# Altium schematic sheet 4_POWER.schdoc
size 749 x 139 mm
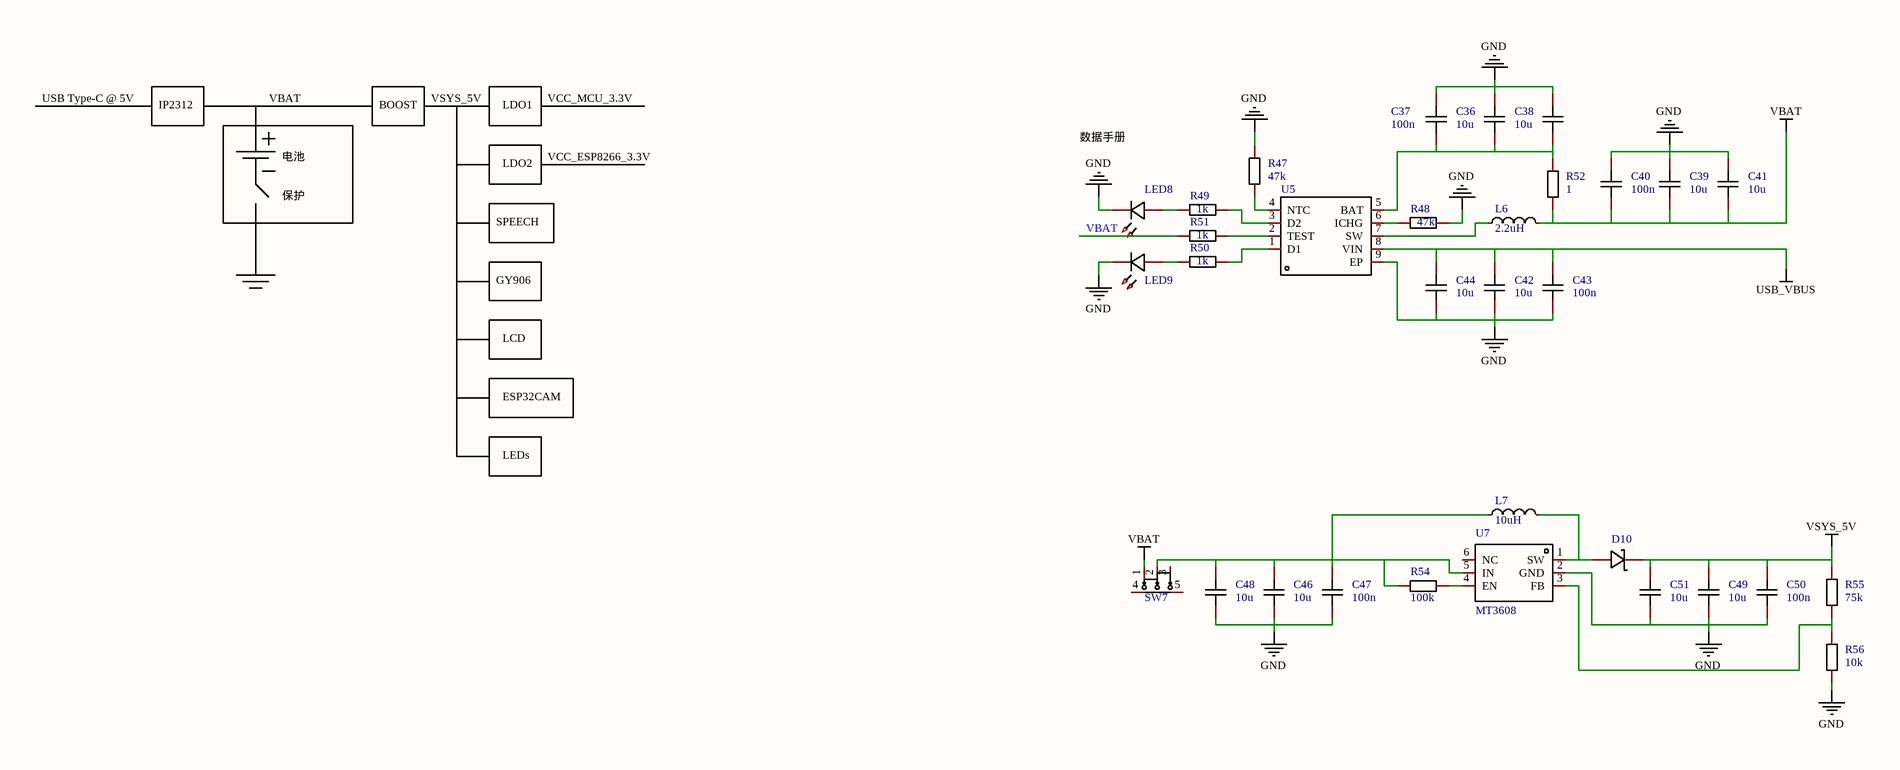
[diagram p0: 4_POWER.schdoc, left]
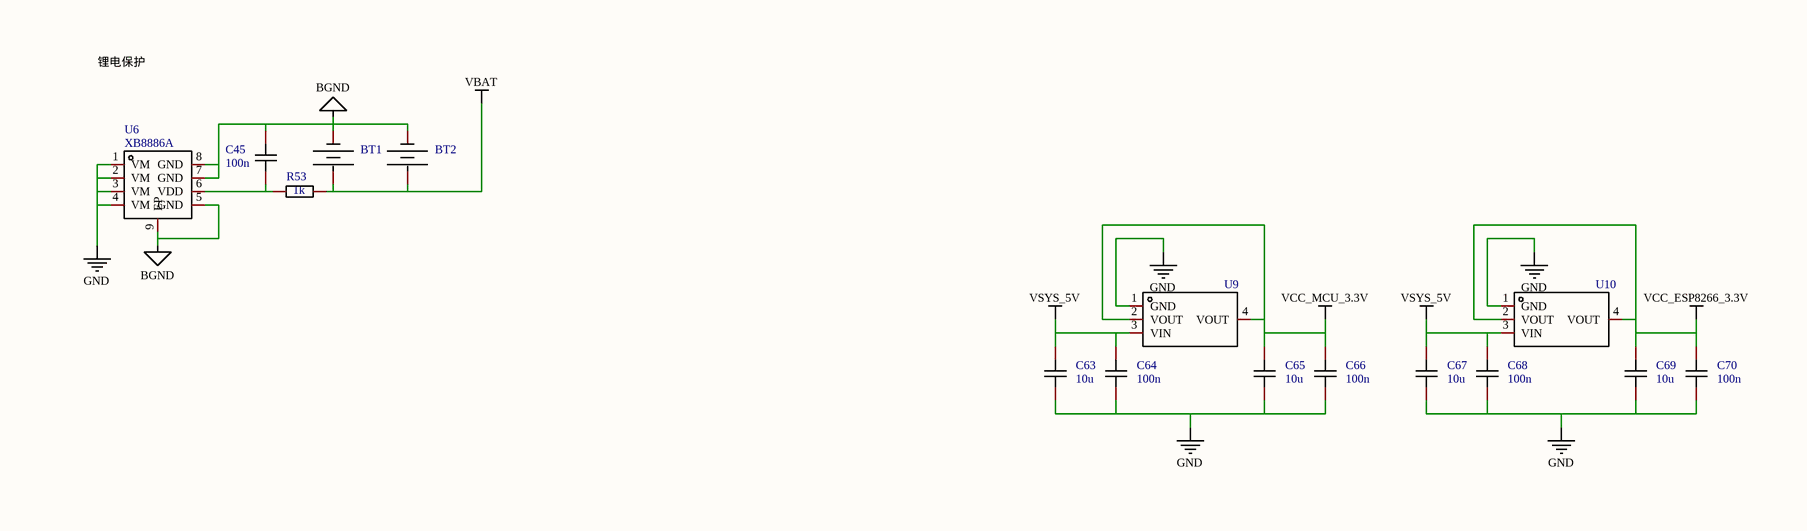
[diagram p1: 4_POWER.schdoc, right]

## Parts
BT1  1028  [BAT-TH_KEYSTONE-1028]  (value not drawn)
BT2  1028  [BAT-TH_KEYSTONE-1028]  (value not drawn)
C36  10u  [C0603]
C37  100n  [C0603]
C38  10u  [C0603]
C39  10u  [C0603]
C40  100n  [C0603]
C41  10u  [C0603]
C42  10u  [C0603]
C43  100n  [C0603]
C44  10u  [C0603]
C45  100n  [C0603]
C46  10u  [C0603]
C47  100n  [C0603]
C48  10u  [C0603]
C49  10u  [C0603]
C50  100n  [C0603]
C51  10u  [C0603]
C63  10u  [C0603]
C64  100n  [C0603]
C65  10u  [C0603]
C66  100n  [C0603]
C67  10u  [C0603]
C68  100n  [C0603]
C69  10u  [C0603]
C70  100n  [C0603]
D10  SS34  [SMA_L4.3-W2.6-LS5.2-RD]  (value not drawn)
L6  2.2uH  [IND-SMD_L7.0-W6.6]
L7  10uH  [IND-SMD_L7.1-W6.6]
LED8  LED_0603-G  [LED_0603]  (value not drawn)
LED9  LED_0603-G  [LED_0603]  (value not drawn)
R47  47k  [R0603]
R48  47k  [R0603]
R49  1k  [R0603]
R50  1k  [R0603]
R51  1k  [R0603]
R52  1  [R0603]
R53  1k  [R0603]
R54  100k  [R0603]
R55  75k  [R0603]
R56  10k  [R0603]
SW7  SS-12D11L3  [SW-TH_SS-12D11L3]  (value not drawn)
U5  IP2312U_VSET  [SOP-8_L4.9-W3.9-P1.27-LS6.0-BL-EP]  (value not drawn)
U6  XB8886A  [SOIC-8_L5.0-W4.0-P1.27-LS6.0-BL-EP2.0]
U7  MT3608  [SOT-23-6_L2.9-W1.6-P0.95-LS2.8-BL]
U9  AMS1117-3.3  [SOT-223-3_L6.5-W3.4-P2.30-LS7.0-BR]  (value not drawn)
U10  AMS1117-3.3  [SOT-223-3_L6.5-W3.4-P2.30-LS7.0-BR]  (value not drawn)

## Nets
BGND: BT1.2(-) BT2.2(-) C45.2 U6.5(GND) U6.7(GND) U6.8(GND) U6.9(EP)
GND: C36.2 C37.2 C38.2 C39.2 C40.2 C41.2 C42.2 C43.2 C44.2 C46.2 C47.2 C48.2 C49.2 C50.2 C51.2 C63.1 C64.1 C65.1 C66.1 C67.1 C68.1 C69.1 C70.1 LED8.1(C) LED9.1(C) R47.2 R48.2 R56.1 U5.9(EP) U6.1(VM) U6.2(VM) U6.3(VM) U6.4(VM) U7.2(GND) U9.1(GND) U10.1(GND)
USB_VBUS: C42.1 C43.1 C44.1 U5.8(VIN)
VBAT: BT1.1(+) BT2.1(+) C39.1 C40.1 C41.1 L6.2 R51.1 R52.1 R53.2 SW7.1
VCC_ESP8266_3.3V: C69.2 C70.2 U10.2(VOUT) U10.4(VOUT)
VCC_MCU_3.3V: C65.2 C66.2 U9.2(VOUT) U9.4(VOUT)
VSYS_5V: C49.1 C50.1 C51.1 C63.2 C64.2 C67.2 C68.2 D10.1(K) R55.2 U9.3(VIN) U10.3(VIN)
NetC36_1: C36.1 C37.1 C38.1 R52.2 U5.5(BAT)
NetC45_1: C45.1 R53.1 U6.6(VDD)
NetC46_1: C46.1 C47.1 C48.1 L7.1 R54.1 SW7.2 U7.5(IN)
NetD10_2: D10.2(A) L7.2 U7.1(SW)
NetL6_1: L6.1 U5.7(SW)
NetLED8_2: LED8.2(A) R49.1
NetLED9_2: LED9.2(A) R50.1
NetR47_1: R47.1 U5.4(NTC)
NetR48_1: R48.1 U5.6(ICHG)
NetR49_2: R49.2 U5.3(D2)
NetR50_2: R50.2 U5.1(D1)
NetR51_2: R51.2 U5.2(TEST)
NetR54_2: R54.2 U7.4(EN)
NetR55_1: R55.1 R56.2 U7.3(FB)

Not connected (* = marked no-connect by the designer): SW7 3 4 5; U7 6(NC)

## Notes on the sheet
- USB Type-C @ 5V
- IP2312
- VBAT
- BOOST
- VSYS_5V
- LDO1
- VCC_MCU_3.3V
- 锂电保护
- 电池
- LDO2
- VCC_ESP8266_3.3V
- 数据手册
- 保护
- SPEECH
- GY906
- LCD
- ESP32CAM
- LEDs

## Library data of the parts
BT1 BT2 = 1028: Manufacturer: Keystone; Add into BOM: yes
C36-C51 C63-C70 = CAP_0603: Symbol: CapAcitance; Convert to PCB: yes
D10 = SS34_C8678: 二极管配置:独立式;直流反向耐压(Vr):40V;平均整流电流(Io):3A;正向压降(Vf):550mV@3A;; Manufacturer: MDD; Add into BOM: yes; Diode Configuration: 独立式; Reverse Voltage (Vr): 40V; Average Rectified Current (Io): 3A; Reverse Leakage Current (Ir): 500uA@40V
L6 = MWSA0603S-2R2MT: 电感值:2.2uH;精度:±20%;额定电流:9.5A;; Manufacturer: Sunlord(顺络); Add into BOM: yes; Tolerance: ±20%; Rated Current: 9.5A; DC Resistance (DCR): 15mΩ
L7 = MWSA0603S-100MT: 电感值:10uH;精度:±20%;额定电流:4.5A;; Manufacturer: Sunlord(顺络); Symbol: MWSA0603-100MT; Add into BOM: yes; Tolerance: ±20%; Rated Current: 4.5A; DC Resistance (DCR): 67mΩ
LED8 LED9 = LED_0603-G: Symbol: LED_G; Convert to PCB: yes
R47-R56 = Res_0603: Symbol: 电阻; Convert to PCB: yes
SW7 = SS-12D11L3: 额定电流(DC):3A;额定电压(DC):125V;额定电流(AC):3A;额定电压(AC):125V;电路结构:单刀双掷;安装方式:弯插;机械寿命:1万次;开关颜色:黑色;; Manufacturer: XKB Connectivity(中国星坤); Add into BOM: yes; Current Rating (DC): 3A; Voltage Rating (DC): 125V; Circuit: 单刀双掷; Mechanical Life: 1万次; Actuator Color: 黑色; Actuator Style: 矩形柱状; Pin Style: PC引脚; Switch Length: 13.5mm; Switch Width: 6.6mm; Switch Height: 6.3mm
U5 = IP2312U_VSET: Manufacturer: INJOINIC(英集芯); Symbol: IP2312; Add into BOM: yes
U6 = XB8886A: Manufacturer: xysemi(赛芯微); Add into BOM: yes
U7 = MT3608: 功能类型:升压型;同步整流:-;输出通道数:1;拓扑结构:升压式;输入电压:2V~24V;输出电压:28V;输出电流(最大值):-;开关频率:1.2MHz;; Manufacturer: 西安航天民芯; Add into BOM: yes; Function: 升压型; Number of Outputs: 1; Topology: 升压式; Input Voltage: 2V~24V; Output Voltage: 28V; Switching Frequency: 1.2MHz
U9 U10 = AMS1117-3.3_C6186: 输出类型:固定;输出极性:正;最大输入电压:-;输出电压:3.3V;输出电流:1A;电源纹波抑制比(PSRR):72dB@(120Hz);; Manufacturer: AMS; Add into BOM: yes; Output Type: 固定; Output Polarity: 正; Number of Outputs: 1; Output Voltage: 3.3V; Dropout Voltage: 1.3V@(800mA); Output Current: 1A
